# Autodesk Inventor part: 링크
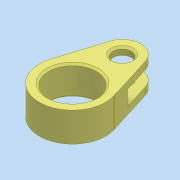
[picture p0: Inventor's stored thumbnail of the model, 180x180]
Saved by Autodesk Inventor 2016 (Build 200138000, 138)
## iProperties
Created: 2024-08
Part Number: 링크
Material: 일반
Document SubType Name: Modeling
Designer: pc-7
Density: 1 g/cm^3
Appearance: 기본값
Author: jhkim
Sending System: Autodesk Inventor 2025
Preprocessor: ST-DEVELOPER v20
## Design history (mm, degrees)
node "링크1"
node "솔리드2"
node "솔리드1"
